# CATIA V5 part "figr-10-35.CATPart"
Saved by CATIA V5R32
Part number: Part1
Bounding box of the stored display mesh (mm): x -80 to 120, y 0 to 190, z 0 to 170
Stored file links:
  D:\PROJECTS\Project 2022\CATIA V5 6R 2022\Resources\Part Files\c10_catia_v5_6r2022_prt\c10_catia_v5_6r2022_prt\figr-10-35.CATPart
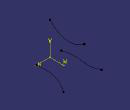
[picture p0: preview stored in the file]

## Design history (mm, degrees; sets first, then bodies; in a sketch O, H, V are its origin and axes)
Set1
  Sketch1 on xy-plane, origin (0, 0, 0), H (1, 0, 0), V (0, 1, 0)
    spline S1 through (-60, 0) (-70, 70) (-70, 170) (-80, 190)
  Sketch2 on yz-plane, origin (0, 0, 0), H (0, 1, 0), V (0, 0, 1)
    spline S1 through (0, 170) (100, 120) (180, 150)
  Sketch3 on xy-plane, origin (0, 0, 0), H (1, 0, 0), V (0, 1, 0)
    spline S1 through (70, 0) (70, 80) (120, 190)
Body1 (main body)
